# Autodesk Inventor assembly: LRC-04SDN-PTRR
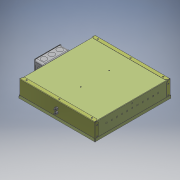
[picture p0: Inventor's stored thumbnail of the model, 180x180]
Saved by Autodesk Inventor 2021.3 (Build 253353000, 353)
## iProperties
load_classification: Lighting
motor: 0 ul
description: 0:0:Super Shallow 4" Downlight - COB LED
manufacturer: 0:0:The Kirlin Company
model: 0:0:LRC-04SDN
url: 0:0:
Part Number: LRC-04SDN-PTRR
Document SubType Name: Assembly
Designer: JChurch
Author: JChurch
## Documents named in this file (7)
- X:\Revit Files\0000-Un-Zipped\COB\LRC-04SDN-PTR\LRC-04SDN-PTRR.iam
- X:\INVENTOR\830\830520-00-00.ipt
- X:\INVENTOR\885\885000-00-00.iam
- X:\INVENTOR\750\750472-00-00.iam
- X:\INVENTOR\725\725383-00-00.ipt
- X:\INVENTOR\501\501087-00-00.ipt
- X:\Revit Files\0000-Un-Zipped\COB\LRC-04SDN-PTR\LRC-04SDN-PTRR_Substitute_1.ipt
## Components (9 placed, 6 different names)
1. 830520-00-00:1 — Mate:1, Mate:2, Mate:3, Mate:4, Mate:5, Angle:1, Insert:2
2. 885000-00-00:1 [sub-assembly] — Mate:4, Mate:5, Angle:1
3. 750472-00-00:1 [sub-assembly] — Insert:1, Insert:2, Insert:3, Insert:4, Insert:5, Insert:6
4. 725383-00-00:1 — Insert:1
5. 501087-00-00:1 — Insert:3
6. 501087-00-00:2 — Insert:4
7. 501087-00-00:3 — Insert:5
8. 501087-00-00:4 — Insert:6
9. LRC-04SDN-PTRR_Substitute_1:1
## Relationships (12: Insert 6, Mate 5, Angle 1)
- Mate:1: 830520-00-00:1
- Mate:2: 830520-00-00:1
- Mate:3: 830520-00-00:1
- Mate:4: 830520-00-00:1 ↔ 885000-00-00:1
- Mate:5: 830520-00-00:1 ↔ 885000-00-00:1
- Angle:1: 830520-00-00:1 ↔ 885000-00-00:1
- Insert:1: 750472-00-00:1 ↔ 725383-00-00:1
- Insert:2: 830520-00-00:1 ↔ 750472-00-00:1
- Insert:3: 750472-00-00:1 ↔ 501087-00-00:1
- Insert:4: 750472-00-00:1 ↔ 501087-00-00:2
- Insert:5: 750472-00-00:1 ↔ 501087-00-00:3
- Insert:6: 750472-00-00:1 ↔ 501087-00-00:4
